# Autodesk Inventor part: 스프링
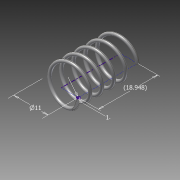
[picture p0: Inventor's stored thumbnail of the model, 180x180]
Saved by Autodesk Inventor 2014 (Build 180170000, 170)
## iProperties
Created: 2015-10
Part Number: 스프링
Material: 강철, 연강
Document SubType Name: Modeling
Designer: Owner
Density: 7.86 g/cm^3
Appearance: 강철
Mass: 1.05526 g
Surface Area: 5.43266 cm^2
Volume: 0.134257 cm^3
Author: Owner
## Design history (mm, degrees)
sketch "스케치1"
  geometry: L1 (0, 0)-(5.5, 0); L2 (5.5, 0)-(5.5, 18.948); L3 (5.5, 18.948)-(0, 18.948); L4 (0, 18.948)-(0, 0); C1 r 0.5 at (5.5, 0)
  constraints: 8 end point, 2 parallel, 1 centre point, 1 coincident, 1 horizontal, 1 perpendicular
  dimensions: "d0" = 1 diameter of C1; "d1" = 18.94782 distance of L1.end L2.end (derived); "d2" = 11 diameter of L2 L4
feature "코일1" sketch "스케치1" pitch "d3" = 10; turns "d5" = 5; dims "d4" = 18.94782 (= d1), "d6" = 0, angle "d7" = 90 deg, angle "d8" = 90 deg, "d9" = 0, "d10" = 0
sketch "스케치2"
  geometry: L1 (-6, 0)-(-5, 0) reference; 1 further point
  constraints: 1 horizontal alignment
extrude "돌출1" cut sketch "스케치2" stored distance "d11" = 10; taper "d12" = 0 deg
node "작업 평면1"
node "작업 평면2"
sketch "스케치3"
  geometry: L1 (-5, 0)-(-6, 0) reference; 1 further point
  constraints: 1 horizontal alignment
extrude "돌출2" cut sketch "스케치3" stored distance "d13" = 10; taper "d14" = 0 deg
node "솔리드1"
node "절단 모서리 투영1"
node "절단 모서리 투영2"
